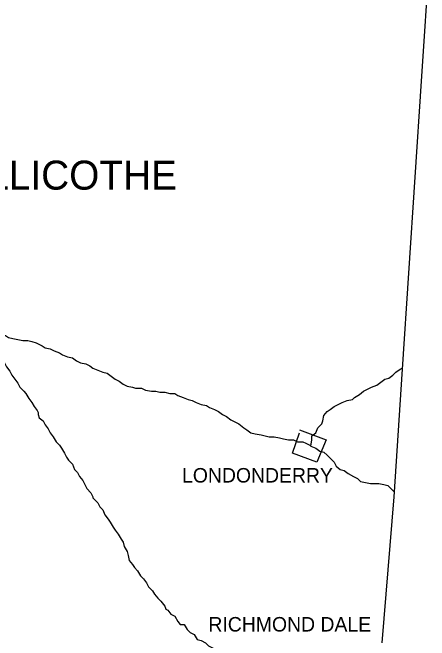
# Model space of a CAD drawing. Extents: x 0 to 40.2, y 0 to 22.
# Drawn here: x 6.366 to 6.926, y 18.548 to 19.393 of the extents above; entities that cross this region are included whole.
import ezdxf

# ---------------------------------------------------------------- set-up
doc = ezdxf.new("R2010")
doc.units = 0
doc.layers.add('Default', color=7, linetype='Continuous')

msp = doc.modelspace()

# ---------------------------------------------------------------- linework, layer by layer
at = {"layer": 'Default'}
for points in [[(6.92646, 19.46942), (6.91556, 19.30036), (6.88965, 18.91315), (6.87874, 18.74135), (6.86238, 18.54502)], [(6.34292, 18.96087), (6.34974, 18.96087), (6.35655, 18.95814), (6.36064, 18.95541), (6.3661, 18.95405), (6.37291, 18.95268), (6.37973, 18.95132), (6.38655, 18.95132), (6.392, 18.94996), (6.39746, 18.94859), (6.40564, 18.9445), (6.40973, 18.94178), (6.41654, 18.94041), (6.422, 18.93769), (6.42881, 18.93496), (6.43291, 18.93223), (6.43972, 18.92951), (6.44654, 18.92814), (6.45199, 18.92405), (6.45745, 18.92133), (6.46426, 18.91996), (6.46972, 18.91724)], [(6.34701, 18.9445), (6.34837, 18.93769), (6.34837, 18.93223), (6.3511, 18.92542), (6.35519, 18.92133), (6.35792, 18.91587), (6.36201, 18.91042), (6.36473, 18.90497), (6.36882, 18.89951), (6.37291, 18.89406), (6.37564, 18.8886), (6.3811, 18.88315), (6.38382, 18.88042), (6.38791, 18.87361), (6.392, 18.86815), (6.39473, 18.8627), (6.39882, 18.85725), (6.40018, 18.85452), (6.40018, 18.85179)], [(6.46972, 18.91724), (6.47381, 18.91451), (6.48062, 18.91178), (6.48744, 18.90906), (6.4929, 18.90769), (6.49835, 18.9036), (6.5038, 18.89951), (6.50926, 18.89678), (6.51471, 18.89269), (6.52016, 18.88997), (6.52698, 18.8886), (6.53107, 18.88724), (6.53925, 18.88724), (6.54471, 18.88451), (6.55289, 18.88315), (6.55834, 18.88315), (6.56379, 18.88179), (6.57061, 18.88179), (6.57743, 18.88042), (6.58424, 18.88042), (6.58834, 18.8777), (6.59515, 18.87497), (6.60197, 18.87224), (6.60742, 18.87088), (6.61288, 18.86815), (6.61969, 18.86543), (6.62651, 18.86406), (6.6306, 18.86134), (6.63742, 18.85861), (6.64287, 18.85588), (6.64833, 18.85179), (6.65378, 18.84906), (6.65923, 18.84497), (6.66469, 18.84225), (6.67014, 18.83952), (6.67696, 18.83407), (6.68105, 18.83134), (6.6865, 18.82725), (6.69196, 18.82589), (6.70014, 18.82452), (6.70559, 18.82316), (6.71104, 18.8218), (6.71786, 18.8218), (6.72468, 18.82043), (6.73013, 18.81907), (6.73695, 18.81771), (6.74377, 18.81771), (6.74922, 18.81498), (6.75604, 18.81498), (6.76013, 18.81362), (6.76558, 18.81089), (6.76694, 18.80953)], [(6.76694, 18.80953), (6.76831, 18.81771), (6.76831, 18.82316), (6.77376, 18.82725), (6.77649, 18.83407), (6.78194, 18.83952), (6.7833, 18.84361), (6.78467, 18.85043), (6.78876, 18.85588), (6.79285, 18.85861), (6.7983, 18.8627), (6.80376, 18.86543), (6.80921, 18.86815), (6.81603, 18.87088), (6.82284, 18.87224), (6.82557, 18.87497), (6.83239, 18.87906), (6.83784, 18.88315), (6.84329, 18.88588), (6.84875, 18.8886), (6.85557, 18.89133), (6.86102, 18.89542), (6.86647, 18.89951), (6.87193, 18.90087), (6.87738, 18.90497), (6.88147, 18.90906), (6.88692, 18.91315), (6.88965, 18.91451), (6.88965, 18.91451)], [(6.40018, 18.85179), (6.40155, 18.8477), (6.407, 18.84361), (6.40973, 18.83816), (6.41382, 18.8327), (6.41654, 18.82725), (6.42063, 18.8218), (6.42472, 18.81498), (6.42881, 18.81089), (6.43154, 18.8068), (6.43563, 18.79998), (6.43836, 18.79453), (6.44109, 18.79044), (6.44654, 18.78498), (6.44927, 18.77817), (6.45336, 18.77408), (6.45608, 18.76862), (6.46017, 18.76317), (6.4629, 18.75772), (6.46563, 18.75226), (6.47108, 18.74681), (6.47381, 18.74135), (6.47381, 18.73999), (6.47517, 18.73863)], [(6.75195, 18.83134), (6.78739, 18.81771), (6.77512, 18.78771), (6.7424, 18.79998), (6.75195, 18.82725)], [(6.76694, 18.80953), (6.77376, 18.8068), (6.77921, 18.80271), (6.78467, 18.80135), (6.78876, 18.79725), (6.79285, 18.79316), (6.7983, 18.78771), (6.80103, 18.78226), (6.80648, 18.77817), (6.81194, 18.7768), (6.81739, 18.77271), (6.82421, 18.76862), (6.82966, 18.7659), (6.83375, 18.76181), (6.84057, 18.76044), (6.84739, 18.75908), (6.85284, 18.75908), (6.85829, 18.75908), (6.86511, 18.75772), (6.87056, 18.75635), (6.87465, 18.75226), (6.87874, 18.74817)], [(6.47517, 18.73863), (6.48062, 18.73317), (6.48335, 18.72772), (6.48744, 18.72363), (6.49017, 18.71681), (6.49426, 18.71136), (6.49699, 18.70727), (6.50108, 18.70045), (6.5038, 18.69636), (6.50789, 18.69091), (6.51198, 18.68409), (6.51471, 18.68), (6.51607, 18.67455), (6.52016, 18.66773), (6.52153, 18.66228), (6.52289, 18.65546), (6.52698, 18.65001), (6.52971, 18.64592), (6.5338, 18.64183), (6.53789, 18.63501), (6.54198, 18.63092), (6.54607, 18.62546), (6.5488, 18.62001), (6.55425, 18.61456), (6.55698, 18.61047), (6.56107, 18.60501), (6.56516, 18.60092), (6.57061, 18.59411), (6.57197, 18.59002), (6.5747, 18.58865)], [(6.5747, 18.58865), (6.57879, 18.5832), (6.58424, 18.58047), (6.58834, 18.57365), (6.59106, 18.56956), (6.59652, 18.56956), (6.60061, 18.56275), (6.6047, 18.55866), (6.61015, 18.55593), (6.61424, 18.54911), (6.61969, 18.54775), (6.62515, 18.54502), (6.62924, 18.54093), (6.63469, 18.53821), (6.64151, 18.53548), (6.6456, 18.53275), (6.65242, 18.53139), (6.65651, 18.52593), (6.65651, 18.52457)]]:
    msp.add_lwpolyline(points, dxfattribs=at)

# ---------------------------------------------------------------- texts
for s, height, p in [('CHILLICOTHE', 0.0390047, (6.24203, 19.15447)), ('LONDONDERRY', 0.0195024, (6.59379, 18.76044)), ('RICHMOND DALE', 0.0195024, (6.62924, 18.56002))]:
    msp.add_text(s, height=height, dxfattribs=at).set_placement(p)

doc.saveas('drawing.dxf')
